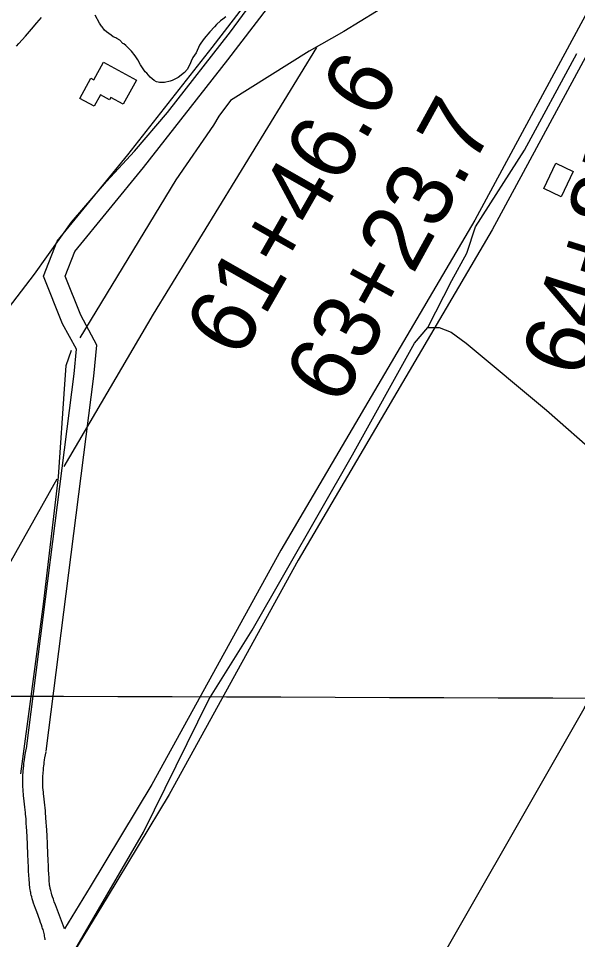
# Model space of a CAD drawing. Extents: x 3146026 to 3183936, y 897894 to 923344.
# Drawn here: x 3158605 to 3159445, y 909043 to 910425 of the extents above; entities that cross this region are included whole.
import ezdxf

# ---------------------------------------------------------------- set-up
doc = ezdxf.new("R2010")
doc.units = 0
for name, color, linetype in [('V-BLDG-OTLN', 7, 'Continuous'), ('V-GRID-MAJR', 7, 'Continuous'), ('V-ROAD-CNTR', 7, 'Continuous'), ('V-SITE-VEGE', 7, 'Continuous'), ('V-SURV-IDEN', 7, 'Continuous'), ('V-TOPO-SHOR', 7, 'Continuous')]:
    doc.layers.add(name, color=color, linetype=linetype)

msp = doc.modelspace()

# ---------------------------------------------------------------- linework, layer by layer
at = {"layer": 'V-BLDG-OTLN'}
for points in [[(3158782.217000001, 910332.6629999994), (3158762.423000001, 910296.3189999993), (3158743.872000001, 910306.4239999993), (3158741.978000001, 910302.9449999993), (3158728.242000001, 910310.4259999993), (3158718.926000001, 910293.3209999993), (3158697.362000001, 910305.0619999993), (3158713.929000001, 910335.4769999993), (3158718.256000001, 910333.1219999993), (3158732.696000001, 910359.6329999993)], [(3159394.217000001, 910169.7279999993), (3159412.032000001, 910207.7269999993), (3159438.146000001, 910195.4839999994), (3159420.331000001, 910157.4849999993)]]:
    msp.add_lwpolyline(points, close=True, dxfattribs=at)
at = {"layer": 'V-GRID-MAJR'}
msp.add_spline([(3150267.842, 909437.3570000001), (3155490.4390000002, 909418.746), (3160713.04, 909400.895), (3165935.643, 909383.804), (3171158.249, 909367.4720000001), (3176380.857, 909351.9), (3181603.467, 909337.087), (3181603.468, 909337.087)], degree=3, dxfattribs=at)
at = {"layer": 'V-ROAD-CNTR'}
for points in [[(3158617.004729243, 909329.1573139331), (3158688.7305857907, 909891.6731888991), (3158692.223578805, 909928.5461151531), (3158671.382620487, 909966.9510383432), (3158642.861677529, 910038.141895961), (3158663.350636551, 910090.584791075), (3158769.5314241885, 910220.2855316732), (3158895.8321715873, 910381.430209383), (3158998.4969662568, 910515.1269419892), (3159065.352832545, 910604.3197636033)], [(3158646.7646697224, 909325.3633215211), (3158718.550526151, 909888.3611955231), (3158722.9515173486, 909934.8181026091), (3158698.5825660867, 909979.7270127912), (3158675.1236130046, 910038.2798956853), (3158689.568584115, 910075.250821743), (3158792.9473773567, 910201.5275691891), (3158919.536124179, 910363.0402461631), (3159022.3969184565, 910496.9949782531), (3159089.356784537, 910586.3257995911)], [(3159506.2809506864, 910459.1050540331), (3159316.5073302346, 910107.7057568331), (3159025.393912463, 909612.1957478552), (3158831.3723005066, 909260.0594521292), (3158738.308486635, 909106.358759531), (3158599.890763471, 908878.6652149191)], [(3159473.1550169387, 910460.9010504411), (3159290.367382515, 910122.4357273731), (3158999.317964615, 909627.0357181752), (3158805.3923524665, 909275.0734221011), (3158712.6605379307, 909121.9207284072), (3158674.190614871, 909058.6388549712)], [(3158602.402758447, 910383.4572053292), (3158605.7867516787, 910387.2491977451), (3158610.8067416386, 910392.9491863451), (3158615.767731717, 910398.6781748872), (3158624.834713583, 910409.224153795), (3158632.7506977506, 910418.4341353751), (3158639.670683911, 910426.5191192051)], [(3158612.119739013, 909292.8793864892), (3158612.279738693, 909295.2083818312), (3158612.648737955, 909299.6013730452), (3158613.0407371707, 909303.469365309), (3158613.430736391, 909306.838358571), (3158613.8057356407, 909309.779352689), (3158614.1627349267, 909312.3723475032), (3158614.8237336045, 909316.8023386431), (3158615.367732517, 909320.1693319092), (3158616.228730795, 909325.1353219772), (3158617.1397289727, 909330.013312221)], [(3158642.0496791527, 909290.8253905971), (3158642.1936788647, 909292.9243863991), (3158642.5226782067, 909296.8333785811), (3158642.866677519, 909300.2313717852), (3158643.2126768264, 909303.2183658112), (3158643.545676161, 909305.839360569), (3158643.858675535, 909308.112356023), (3158644.467674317, 909312.1963478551), (3158644.9556733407, 909315.2133418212), (3158645.7546717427, 909319.8193326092), (3158646.6296699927, 909324.5073232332)], [(3158645.3336725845, 909042.3948874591), (3158645.206672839, 909043.4018854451), (3158644.8796734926, 909045.5788810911), (3158644.5056742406, 909047.6608769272), (3158644.0826750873, 909049.7088728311), (3158643.617676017, 909051.7218688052), (3158643.118677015, 909053.6968648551), (3158642.5916780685, 909055.634860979), (3158642.0436791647, 909057.5288571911), (3158641.476680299, 909059.3898534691), (3158640.9076814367, 909061.1788498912), (3158639.6936838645, 909064.8008426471), (3158638.4896862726, 909068.2128358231), (3158637.309688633, 909071.4428293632), (3158632.541698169, 909084.104804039), (3158630.731701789, 909089.014794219), (3158629.181704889, 909093.3987854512), (3158627.869707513, 909097.303777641), (3158626.772709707, 909100.7767706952), (3158625.8617115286, 909103.8617645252), (3158625.1107130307, 909106.5937590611), (3158624.4907142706, 909109.016754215), (3158623.9847152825, 909111.1577499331), (3158623.5697161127, 909113.0427461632), (3158623.218716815, 909114.7597427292), (3158622.692717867, 909117.639736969), (3158622.339718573, 909119.8777324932), (3158622.0997190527, 909121.6217290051), (3158621.807719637, 909124.147723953), (3158621.5877200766, 909126.6537189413), (3158621.126720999, 909133.2697057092), (3158620.741721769, 909139.4126934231), (3158620.412722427, 909145.176681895), (3158620.126722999, 909150.5936710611), (3158619.640723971, 909160.7156508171), (3158619.2477247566, 909169.5826330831), (3158618.584726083, 909185.0606021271), (3158618.060727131, 909196.6285789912), (3158617.627727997, 909205.2655617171), (3158617.2697287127, 909211.7135488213), (3158616.9787292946, 909216.5195392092), (3158616.498730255, 909223.7285247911), (3158615.957731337, 909230.8885104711), (3158615.7707317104, 909233.080506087), (3158615.353732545, 909237.3244975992), (3158614.943733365, 909241.0534901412), (3158613.351736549, 909254.6084630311), (3158612.968737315, 909258.1154560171), (3158612.697737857, 909260.8004506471), (3158612.336738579, 909264.8224426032), (3158612.0417391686, 909268.877434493), (3158611.925739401, 909270.9114304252), (3158611.7747397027, 909274.664422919), (3158611.7057398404, 909278.2184158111), (3158611.7037398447, 909281.537409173), (3158611.753739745, 909284.6454029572), (3158611.8457395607, 909287.548397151), (3158611.9687393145, 909290.261391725), (3158612.109739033, 909292.7153868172)], [(3158674.190614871, 909058.6388549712), (3158660.6536419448, 909094.578783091), (3158658.949645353, 909099.204773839), (3158657.5436481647, 909103.1767658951), (3158656.395650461, 909106.597759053), (3158655.4646523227, 909109.544753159), (3158654.7136538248, 909112.0877480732), (3158654.108655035, 909114.2877436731), (3158653.622656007, 909116.188739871), (3158653.232656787, 909117.8337365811), (3158652.917657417, 909119.268733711), (3158652.6746579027, 909120.457731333), (3158652.2706587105, 909122.6717269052), (3158652.019659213, 909124.2617237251), (3158651.863659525, 909125.3937214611), (3158651.6556599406, 909127.1857178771), (3158651.495660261, 909129.0077142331), (3158651.060661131, 909135.2497017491), (3158650.687661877, 909141.2066898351), (3158650.3666625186, 909146.8226786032), (3158650.0886630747, 909152.1036680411), (3158649.608664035, 909162.0996480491), (3158649.2196648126, 909170.888630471), (3158648.5546661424, 909186.3805994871), (3158648.0266671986, 909198.0585761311), (3158647.585668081, 909206.8475585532), (3158647.219668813, 909213.4515453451), (3158646.9186694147, 909218.4235354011), (3158646.4226704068, 909225.854520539), (3158645.861671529, 909233.296505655), (3158645.6446719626, 909235.8245005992), (3158645.193672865, 909240.4304913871), (3158644.751673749, 909244.443483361), (3158643.1616769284, 909257.9864562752), (3158642.804677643, 909261.2534497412), (3158642.561678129, 909263.6504449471), (3158642.238678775, 909267.250437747), (3158641.9796792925, 909270.8174306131), (3158641.8916794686, 909272.3674275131), (3158641.762679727, 909275.5584211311), (3158641.7056798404, 909278.5184152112), (3158641.7036798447, 909281.3074096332), (3158641.745679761, 909283.9294043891), (3158641.8236796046, 909286.3963994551), (3158641.928679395, 909288.7213948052), (3158642.0596791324, 909290.989390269)]]:
    msp.add_lwpolyline(points, dxfattribs=at)
at = {"layer": 'V-SITE-VEGE'}
msp.add_lwpolyline([(3158916.453000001, 910427.5689999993), (3158912.275000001, 910424.1899999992), (3158908.513000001, 910421.6529999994), (3158902.672000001, 910415.7439999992), (3158899.756000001, 910412.3709999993), (3158892.662000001, 910405.1989999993), (3158883.906000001, 910395.0799999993), (3158878.9110000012, 910387.9199999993), (3158877.250000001, 910384.9729999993), (3158871.858000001, 910373.6169999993), (3158866.863000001, 910366.4549999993), (3158864.377000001, 910360.9869999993), (3158862.306000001, 910355.9409999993), (3158858.573000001, 910348.3669999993), (3158854.403000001, 910343.7279999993), (3158845.214000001, 910336.5439999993), (3158843.123000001, 910335.2739999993), (3158836.006000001, 910331.8769999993), (3158833.075000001, 910331.0229999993), (3158824.277000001, 910328.8759999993), (3158817.1440000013, 910328.8369999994), (3158815.045000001, 910329.2449999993), (3158812.521000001, 910330.0679999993), (3158809.157000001, 910331.7269999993), (3158802.832000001, 910337.1479999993), (3158797.766000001, 910342.9929999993), (3158795.654000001, 910345.0799999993), (3158788.464000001, 910355.5289999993), (3158784.646000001, 910363.0599999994), (3158780.419000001, 910368.9109999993), (3158774.924000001, 910376.0109999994), (3158766.486000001, 910384.3569999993), (3158763.535000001, 910386.8569999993), (3158761.852000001, 910387.6889999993), (3158757.211000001, 910392.2779999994), (3158753.000000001, 910394.7729999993), (3158751.315000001, 910396.0199999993), (3158747.528000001, 910397.6789999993), (3158744.1610000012, 910399.7579999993), (3158737.419000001, 910404.7549999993), (3158734.470000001, 910407.2549999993), (3158730.665000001, 910412.6889999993), (3158729.819000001, 910413.5219999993), (3158726.858000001, 910418.1219999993), (3158720.4990000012, 910429.8349999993)], dxfattribs=at)
at = {"layer": 'V-TOPO-SHOR'}
msp.add_line((3159398.338215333, 909837.2993474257), (3159542.6928636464, 909709.7509053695), dxfattribs=at)
for points in [[(3158211.4425147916, 909497.6527779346), (3158321.34257203, 909647.1768487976), (3158436.89225206, 909790.7459287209), (3158629.284171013, 910041.161540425), (3158685.054915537, 910119.5309321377), (3158737.4664544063, 910180.5697452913), (3158779.3040750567, 910225.9194116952), (3158828.7381184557, 910284.1334134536), (3158923.36898816, 910405.0276601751), (3159033.269045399, 910554.5517310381), (3159046.744117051, 910570.1645357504)], [(3158768.1352456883, 908183.366871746), (3158823.376804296, 908269.7908975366), (3159091.322014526, 908753.8920119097), (3159184.710297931, 908917.5594734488), (3159454.744895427, 909389.5675695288), (3159575.801441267, 909598.2515000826), (3159899.336419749, 910182.0093184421), (3160046.4783275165, 910467.050268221), (3160071.677337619, 910509.7241065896), (3160178.1718716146, 910530.9978443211)], [(3159256.1235434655, 910473.2052339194), (3159220.603499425, 910474.8657122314), (3159192.069141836, 910466.1812984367), (3159093.9453508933, 910405.6195840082), (3159041.629200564, 910375.7872557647), (3158923.5599992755, 910301.9603712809), (3158906.2485452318, 910278.464822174), (3158897.907748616, 910264.8942839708), (3158841.3162881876, 910182.9175359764), (3158697.175111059, 909945.7480478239)], [(3158673.9470711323, 909752.573193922), (3158807.7051851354, 909981.3064189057), (3159053.386498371, 910381.284194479)], [(3159220.1461493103, 909961.018015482), (3159256.1241675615, 910031.9245440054), (3159278.2454039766, 910072.7125006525), (3159291.625009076, 910112.2789066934), (3159365.05074681, 910227.1990379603), (3159443.6298060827, 910372.4667672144)], [(3158359.937294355, 908410.8656832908), (3158357.5705351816, 908431.2500993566), (3158360.185366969, 908447.8744750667), (3158472.8719865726, 908648.1305599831), (3158592.3724840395, 908859.0942006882), (3158793.0478260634, 909203.6446148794), (3158891.1905074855, 909402.8318332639), (3158956.351790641, 909507.0825797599), (3159106.9823529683, 909770.2097647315), (3159199.933541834, 909937.5988084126), (3159220.1461493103, 909961.018015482), (3159236.846867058, 909961.3043371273), (3159254.807306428, 909954.299604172), (3159277.5966526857, 909937.7325239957), (3159398.338215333, 909837.2993474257)], [(3158684.32990022, 909926.489715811), (3158676.466280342, 909903.4713434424), (3158674.290454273, 909875.9485568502), (3158664.823729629, 909736.8458761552), (3158642.3782345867, 909545.8278018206), (3158608.0991777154, 909291.2515490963)], [(3157989.0842399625, 909597.8567723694), (3157958.622206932, 909543.4982775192), (3157958.1641547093, 909526.0913569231), (3157964.9971570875, 909509.9441579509), (3157980.6099618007, 909496.4690862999), (3158405.018437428, 909296.5954916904), (3158578.018386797, 909582.3593388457), (3158663.296810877, 909733.9828937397)]]:
    msp.add_lwpolyline(points, dxfattribs=at)

# ---------------------------------------------------------------- texts
at = {"layer": 'V-SURV-IDEN'}
for s, height, rotation, p in [('61+46.6', 99.99999999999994, 60.239583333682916, (3158937.551396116, 909911.6448134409)), ('64+85.1', 100.00000000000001, 72.50548970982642, (3159453.5279613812, 909882.6256921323)), ('63+23.7', 100.00000000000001, 61.20874963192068, (3159088.237940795, 909840.5859584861))]:
    msp.add_text(s, height=height, rotation=rotation, dxfattribs=at).set_placement(p)

doc.saveas('drawing.dxf')
